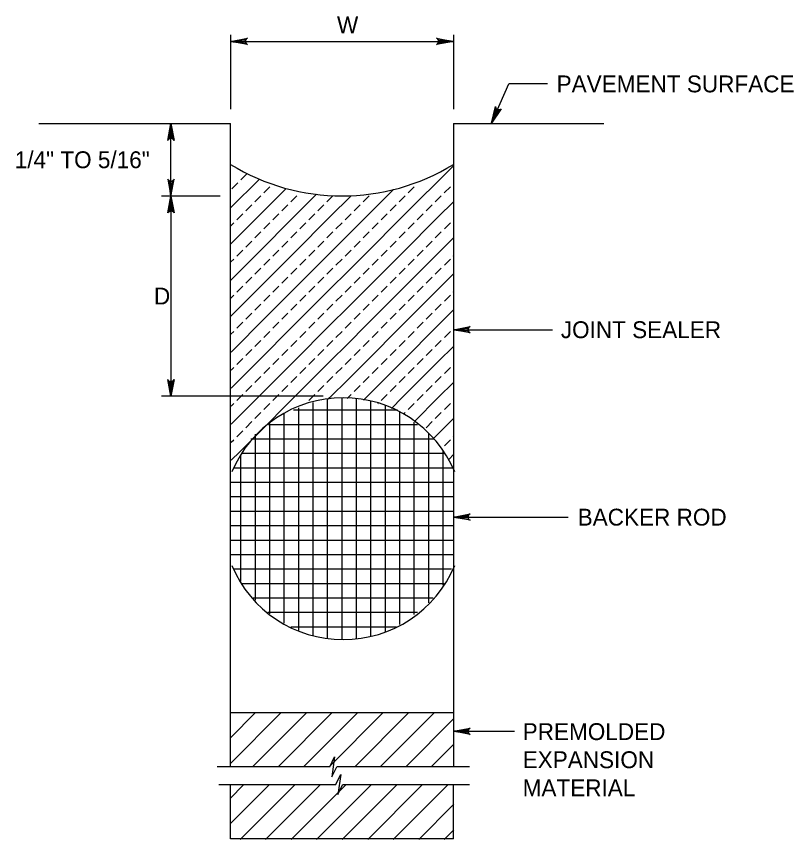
# Model space of a CAD drawing. Extents: x 1.68 to 8.95, y -3.21 to 6.76.
# Drawn here: x 4.101 to 6.867, y 0.817 to 3.746 of the extents above; entities that cross this region are included whole.
import ezdxf

# ---------------------------------------------------------------- set-up
doc = ezdxf.new("R2010")
doc.units = 0
for name, color, linetype in [('DETL-DIMS', 7, 'Continuous'), ('DETL-LINE', 7, 'Continuous'), ('DETL-NOTE', 7, 'Continuous'), ('DETL-PATT', 7, 'Continuous')]:
    doc.layers.add(name, color=color, linetype=linetype)

msp = doc.modelspace()

# ---------------------------------------------------------------- linework, layer by layer
at = {"layer": 'DETL-DIMS'}
for p, q in [((4.863, 3.6802), (4.863, 3.416)), ((5.6563, 3.6802), (5.6563, 3.416)), ((4.863, 3.6573), (5.6563, 3.6573)), ((5.792, 3.3664), (5.8536, 3.5058)), ((5.9915, 3.5058), (5.8536, 3.5058)), ((4.6505, 3.1074), (4.6505, 3.3646)), ((4.6172, 3.1074), (4.8256, 3.1074)), ((4.6505, 3.1074), (4.6505, 2.3943)), ((5.6563, 2.6311), (6.0092, 2.6311)), ((5.1927, 2.3943), (4.6172, 2.3943)), ((5.6563, 1.9641), (6.0653, 1.9641)), ((5.6563, 1.2019), (5.8744, 1.2019))]:
    msp.add_line(p, q, dxfattribs=at)
for points in [[(4.863, 3.6573), (4.923, 3.6685), (4.9184, 3.6653), (4.916, 3.6613), (4.9153, 3.6573), (4.916, 3.6533), (4.9184, 3.6493), (4.923, 3.6461), (4.863, 3.6573), (4.9184, 3.6493), (4.916, 3.6533), (4.863, 3.6573), (4.9153, 3.6573), (4.916, 3.6613), (4.863, 3.6573), (4.9184, 3.6653)], [(4.863, 3.6573), (4.923, 3.6685), (4.9184, 3.6653), (4.916, 3.6613), (4.9153, 3.6573), (4.916, 3.6533), (4.9184, 3.6493), (4.923, 3.6461), (4.863, 3.6573), (4.9184, 3.6493), (4.916, 3.6533), (4.863, 3.6573), (4.9153, 3.6573), (4.916, 3.6613), (4.863, 3.6573), (4.9184, 3.6653)], [(5.6563, 3.6573), (5.5964, 3.6461), (5.601, 3.6493), (5.6034, 3.6533), (5.6041, 3.6573), (5.6034, 3.6613), (5.601, 3.6653), (5.5964, 3.6685), (5.6563, 3.6573), (5.601, 3.6653), (5.6034, 3.6613), (5.6563, 3.6573), (5.6041, 3.6573), (5.6034, 3.6533), (5.6563, 3.6573), (5.601, 3.6493)], [(5.6563, 3.6573), (5.5964, 3.6461), (5.601, 3.6493), (5.6034, 3.6533), (5.6041, 3.6573), (5.6034, 3.6613), (5.601, 3.6653), (5.5964, 3.6685), (5.6563, 3.6573), (5.601, 3.6653), (5.6034, 3.6613), (5.6563, 3.6573), (5.6041, 3.6573), (5.6034, 3.6533), (5.6563, 3.6573), (5.601, 3.6493)], [(5.792, 3.3664), (5.806, 3.4257), (5.807, 3.4202), (5.8097, 3.4164), (5.8131, 3.4141), (5.8171, 3.4131), (5.8217, 3.4137), (5.8265, 3.4166), (5.792, 3.3664), (5.8217, 3.4137), (5.8171, 3.4131), (5.792, 3.3664), (5.8131, 3.4141), (5.8097, 3.4164), (5.792, 3.3664), (5.807, 3.4202)], [(4.6505, 3.3646), (4.6618, 3.3047), (4.6586, 3.3093), (4.6545, 3.3117), (4.6505, 3.3123), (4.6465, 3.3117), (4.6425, 3.3093), (4.6393, 3.3047), (4.6505, 3.3646), (4.6425, 3.3093), (4.6465, 3.3117), (4.6505, 3.3646), (4.6505, 3.3123), (4.6545, 3.3117), (4.6505, 3.3646), (4.6586, 3.3093)], [(4.6507, 3.1064), (4.662, 3.1664), (4.6588, 3.1617), (4.6548, 3.1594), (4.6507, 3.1587), (4.6467, 3.1594), (4.6427, 3.1617), (4.6395, 3.1664), (4.6507, 3.1064), (4.6427, 3.1617), (4.6467, 3.1594), (4.6507, 3.1064), (4.6507, 3.1587), (4.6548, 3.1594), (4.6507, 3.1064), (4.6588, 3.1617)], [(4.6507, 3.1064), (4.662, 3.0465), (4.6588, 3.0511), (4.6548, 3.0535), (4.6507, 3.0542), (4.6467, 3.0535), (4.6427, 3.0511), (4.6395, 3.0465), (4.6507, 3.1064), (4.6427, 3.0511), (4.6467, 3.0535), (4.6507, 3.1064), (4.6507, 3.0542), (4.6548, 3.0535), (4.6507, 3.1064), (4.6588, 3.0511)], [(5.6563, 2.6311), (5.7162, 2.6424), (5.7116, 2.6392), (5.7092, 2.6352), (5.7085, 2.6311), (5.7092, 2.6271), (5.7116, 2.6231), (5.7162, 2.6199), (5.6563, 2.6311), (5.7116, 2.6231), (5.7092, 2.6271), (5.6563, 2.6311), (5.7085, 2.6311), (5.7092, 2.6352), (5.6563, 2.6311), (5.7116, 2.6392)], [(4.6505, 2.3943), (4.6393, 2.4542), (4.6425, 2.4496), (4.6465, 2.4472), (4.6505, 2.4465), (4.6545, 2.4472), (4.6586, 2.4496), (4.6618, 2.4542), (4.6505, 2.3943), (4.6586, 2.4496), (4.6545, 2.4472), (4.6505, 2.3943), (4.6505, 2.4465), (4.6465, 2.4472), (4.6505, 2.3943), (4.6425, 2.4496)], [(5.6563, 1.9641), (5.7162, 1.9753), (5.7116, 1.9721), (5.7092, 1.9681), (5.7085, 1.9641), (5.7092, 1.96), (5.7116, 1.956), (5.7162, 1.9528), (5.6563, 1.9641), (5.7116, 1.956), (5.7092, 1.96), (5.6563, 1.9641), (5.7085, 1.9641), (5.7092, 1.9681), (5.6563, 1.9641), (5.7116, 1.9721)], [(5.6563, 1.9641), (5.7162, 1.9753), (5.7116, 1.9721), (5.7092, 1.9681), (5.7085, 1.9641), (5.7092, 1.96), (5.7116, 1.956), (5.7162, 1.9528), (5.6563, 1.9641), (5.7116, 1.956), (5.7092, 1.96), (5.6563, 1.9641), (5.7085, 1.9641), (5.7092, 1.9681), (5.6563, 1.9641), (5.7116, 1.9721)], [(5.6563, 1.2019), (5.7162, 1.2132), (5.7116, 1.21), (5.7092, 1.2059), (5.7085, 1.2019), (5.7092, 1.1979), (5.7116, 1.1939), (5.7162, 1.1907), (5.6563, 1.2019), (5.7116, 1.1939), (5.7092, 1.1979), (5.6563, 1.2019), (5.7085, 1.2019), (5.7092, 1.2059), (5.6563, 1.2019), (5.7116, 1.21)]]:
    msp.add_lwpolyline(points, dxfattribs=at)
at = {"layer": 'DETL-LINE'}
for p, q in [((4.1808, 3.3646), (4.863, 3.3646)), ((4.863, 1.076), (4.863, 3.3646)), ((5.6563, 3.3646), (5.6563, 1.076)), ((5.6563, 3.3646), (6.1919, 3.3646)), ((5.6562, 3.0218), (5.6565, 3.0221)), ((5.6562, 2.8932), (5.6567, 2.8937)), ((4.864, 2.7439), (4.8741, 2.7539)), ((5.6562, 2.7646), (5.657, 2.7654)), ((5.6562, 2.6361), (5.6572, 2.6371)), ((4.8644, 2.6156), (4.8741, 2.6253)), ((4.8647, 2.4874), (4.8741, 2.4968)), ((5.6562, 2.5075), (5.6575, 2.5088)), ((5.2114, 2.3841), (5.2169, 2.3896)), ((5.2782, 2.3867), (5.2812, 2.3896)), ((5.6562, 2.3789), (5.6577, 2.3804)), ((5.1306, 2.3676), (5.1312, 2.3682)), ((5.3876, 2.3675), (5.3883, 2.3682)), ((4.8955, 2.1968), (4.9598, 2.2611)), ((5.6562, 2.2503), (5.658, 2.2521)), ((4.863, 1.2688), (5.6563, 1.2688)), ((5.216, 1.076), (4.8158, 1.076)), ((5.7135, 1.076), (5.2407, 1.076)), ((5.2369, 1.0117), (4.8217, 1.0117)), ((4.863, 0.8188), (4.863, 1.0117)), ((5.7135, 1.0117), (5.2617, 1.0117)), ((5.6563, 0.8188), (5.6563, 1.0117)), ((5.6563, 0.8188), (4.863, 0.8188))]:
    msp.add_line(p, q, dxfattribs=at)
for points in [[(5.216, 1.076), (5.2332, 1.1112), (5.2235, 1.0398), (5.2407, 1.076)], [(5.2369, 1.0117), (5.255, 1.0487), (5.2453, 0.9773), (5.2617, 1.0117)]]:
    msp.add_lwpolyline(points, dxfattribs=at)
for centre, radius, start, end in [((5.2597, 3.8685), 0.7611, 238.5901, 301.4099), ((5.2642, 1.9586), 0.4304, 22.8516, 157.1484), ((5.2642, 1.9586), 0.4304, 202.8516, 337.1484)]:
    msp.add_arc(centre, radius, start, end, dxfattribs=at)
at = {"layer": 'DETL-PATT'}
for p, q in [((5.4741, 3.0325), (5.6563, 3.2147)), ((4.8632, 3.0645), (4.9654, 3.1667)), ((4.8996, 3.1648), (4.921, 3.1862)), ((4.8674, 3.1327), (4.8889, 3.1541)), ((4.9811, 3.1181), (5.0025, 3.1396)), ((5.4953, 3.1181), (5.5168, 3.1396)), ((5.624, 3.1181), (5.6454, 3.1395)), ((4.9491, 3.0861), (4.9704, 3.1074)), ((4.9598, 3.0325), (5.0611, 3.1338)), ((5.0776, 3.0861), (5.099, 3.1074)), ((5.0883, 3.0325), (5.1687, 3.1129)), ((5.2062, 3.0861), (5.2276, 3.1074)), ((5.2169, 3.0325), (5.2926, 3.1081)), ((5.3348, 3.0861), (5.3561, 3.1074)), ((5.3455, 3.0325), (5.4428, 3.1298)), ((5.4633, 3.0861), (5.4847, 3.1074)), ((5.5919, 3.0861), (5.6133, 3.1074)), ((5.6026, 3.0325), (5.6564, 3.0862)), ((4.9169, 3.0539), (4.9383, 3.0753)), ((5.0455, 3.0539), (5.0669, 3.0753)), ((5.1741, 3.0539), (5.1955, 3.0753)), ((5.3026, 3.0539), (5.3241, 3.0753)), ((5.4312, 3.0539), (5.4526, 3.0753)), ((5.5598, 3.0539), (5.5812, 3.0753)), ((4.8848, 3.0218), (4.8955, 3.0325)), ((4.8955, 3.0325), (4.9062, 3.0432)), ((4.8955, 2.9682), (4.9598, 3.0325)), ((4.9598, 2.9039), (5.0883, 3.0325)), ((5.0133, 3.0218), (5.0241, 3.0325)), ((5.0241, 3.0325), (5.0348, 3.0432)), ((5.0883, 2.9039), (5.2169, 3.0325)), ((5.1419, 3.0218), (5.1526, 3.0325)), ((5.1526, 3.0325), (5.1633, 3.0432)), ((5.2705, 3.0218), (5.2812, 3.0325)), ((5.2812, 3.0325), (5.2919, 3.0432)), ((5.2812, 2.9682), (5.3455, 3.0325)), ((5.3455, 2.9039), (5.4741, 3.0325)), ((5.3991, 3.0218), (5.4098, 3.0325)), ((5.4098, 3.0325), (5.4205, 3.0432)), ((5.4741, 2.9039), (5.6026, 3.0325)), ((5.5276, 3.0218), (5.5383, 3.0325)), ((5.5383, 3.0325), (5.5491, 3.0432)), ((4.8633, 3.0003), (4.8741, 3.0111)), ((4.9812, 2.9896), (5.0026, 3.0111)), ((5.1098, 2.9896), (5.1312, 3.0111)), ((5.2383, 2.9896), (5.2598, 3.0111)), ((5.3669, 2.9896), (5.3883, 3.0111)), ((5.4955, 2.9896), (5.5169, 3.0111)), ((5.6241, 2.9896), (5.6455, 3.0111)), ((4.8635, 2.9362), (4.8955, 2.9682)), ((4.9491, 2.9575), (4.9705, 2.9789)), ((5.0776, 2.9575), (5.0991, 2.9789)), ((5.2062, 2.9575), (5.2276, 2.9789)), ((5.2169, 2.9039), (5.2812, 2.9682)), ((5.3348, 2.9575), (5.3562, 2.9789)), ((5.4633, 2.9575), (5.4848, 2.9789)), ((5.5919, 2.9575), (5.6133, 2.9789)), ((4.9169, 2.9253), (4.9383, 2.9468)), ((5.0455, 2.9253), (5.0669, 2.9468)), ((5.1741, 2.9253), (5.1955, 2.9468)), ((5.3026, 2.9253), (5.3241, 2.9468)), ((5.4312, 2.9253), (5.4526, 2.9468)), ((5.5598, 2.9253), (5.5812, 2.9468)), ((5.6026, 2.9039), (5.6566, 2.9579)), ((4.8848, 2.8932), (4.8955, 2.9039)), ((4.8955, 2.9039), (4.9062, 2.9146)), ((4.8955, 2.8396), (4.9598, 2.9039)), ((4.9598, 2.7753), (5.0883, 2.9039)), ((5.0133, 2.8932), (5.0241, 2.9039)), ((5.0241, 2.9039), (5.0348, 2.9146)), ((5.0883, 2.7753), (5.2169, 2.9039)), ((5.1419, 2.8932), (5.1526, 2.9039)), ((5.1526, 2.9039), (5.1633, 2.9146)), ((5.2705, 2.8932), (5.2812, 2.9039)), ((5.2812, 2.9039), (5.2919, 2.9146)), ((5.2812, 2.8396), (5.3455, 2.9039)), ((5.3455, 2.7753), (5.4741, 2.9039)), ((5.3991, 2.8932), (5.4098, 2.9039)), ((5.4098, 2.9039), (5.4205, 2.9146)), ((5.4741, 2.7753), (5.6026, 2.9039)), ((5.5276, 2.8932), (5.5383, 2.9039)), ((5.5383, 2.9039), (5.5491, 2.9146)), ((4.8637, 2.8721), (4.8741, 2.8825)), ((4.9812, 2.8611), (5.0026, 2.8825)), ((5.1098, 2.8611), (5.1312, 2.8825)), ((5.2383, 2.8611), (5.2598, 2.8825)), ((5.3669, 2.8611), (5.3883, 2.8825)), ((5.4955, 2.8611), (5.5169, 2.8825)), ((5.6241, 2.8611), (5.6455, 2.8825)), ((4.9491, 2.8289), (4.9705, 2.8503)), ((5.0776, 2.8289), (5.0991, 2.8503)), ((5.2062, 2.8289), (5.2276, 2.8503)), ((5.3348, 2.8289), (5.3562, 2.8503)), ((5.4633, 2.8289), (5.4848, 2.8503)), ((5.5919, 2.8289), (5.6133, 2.8503)), ((4.8638, 2.808), (4.8955, 2.8396)), ((4.9169, 2.7968), (4.9383, 2.8182)), ((5.0455, 2.7968), (5.0669, 2.8182)), ((5.1741, 2.7968), (5.1955, 2.8182)), ((5.2169, 2.7753), (5.2812, 2.8396)), ((5.3026, 2.7968), (5.3241, 2.8182)), ((5.4312, 2.7968), (5.4526, 2.8182)), ((5.5598, 2.7968), (5.5812, 2.8182)), ((5.6026, 2.7753), (5.6569, 2.8296)), ((4.8955, 2.7753), (4.9062, 2.7861)), ((5.0241, 2.7753), (5.0348, 2.7861)), ((5.1526, 2.7753), (5.1633, 2.7861)), ((5.2812, 2.7753), (5.2919, 2.7861)), ((5.4098, 2.7753), (5.4205, 2.7861)), ((5.5383, 2.7753), (5.5491, 2.7861)), ((4.8848, 2.7646), (4.8955, 2.7753)), ((4.8955, 2.7111), (4.9598, 2.7753)), ((4.9598, 2.6468), (5.0883, 2.7753)), ((4.9812, 2.7325), (5.0026, 2.7539)), ((5.0133, 2.7646), (5.0241, 2.7753)), ((5.0883, 2.6468), (5.2169, 2.7753)), ((5.1098, 2.7325), (5.1312, 2.7539)), ((5.1419, 2.7646), (5.1526, 2.7753)), ((5.2383, 2.7325), (5.2598, 2.7539)), ((5.2705, 2.7646), (5.2812, 2.7753)), ((5.2812, 2.7111), (5.3455, 2.7753)), ((5.3455, 2.6468), (5.4741, 2.7753)), ((5.3669, 2.7325), (5.3883, 2.7539)), ((5.3991, 2.7646), (5.4098, 2.7753)), ((5.4741, 2.6468), (5.6026, 2.7753)), ((5.4955, 2.7325), (5.5169, 2.7539)), ((5.5276, 2.7646), (5.5383, 2.7753)), ((5.6241, 2.7325), (5.6455, 2.7539)), ((4.8642, 2.6798), (4.8955, 2.7111)), ((4.9491, 2.7003), (4.9705, 2.7218)), ((5.0776, 2.7003), (5.0991, 2.7218)), ((5.2062, 2.7003), (5.2276, 2.7218)), ((5.2169, 2.6468), (5.2812, 2.7111)), ((5.3348, 2.7003), (5.3562, 2.7218)), ((5.4633, 2.7003), (5.4848, 2.7218)), ((5.5919, 2.7003), (5.6133, 2.7218)), ((5.6026, 2.6468), (5.6571, 2.7013)), ((4.9169, 2.6682), (4.9383, 2.6896)), ((5.0455, 2.6682), (5.0669, 2.6896)), ((5.1741, 2.6682), (5.1955, 2.6896)), ((5.3026, 2.6682), (5.3241, 2.6896)), ((5.4312, 2.6682), (5.4526, 2.6896)), ((5.5598, 2.6682), (5.5812, 2.6896)), ((4.8848, 2.6361), (4.8955, 2.6468)), ((4.8955, 2.6468), (4.9062, 2.6575)), ((4.8955, 2.5825), (4.9598, 2.6468)), ((4.9598, 2.5182), (5.0883, 2.6468)), ((5.0133, 2.6361), (5.0241, 2.6468)), ((5.0241, 2.6468), (5.0348, 2.6575)), ((5.0883, 2.5182), (5.2169, 2.6468)), ((5.1419, 2.6361), (5.1526, 2.6468)), ((5.1526, 2.6468), (5.1633, 2.6575)), ((5.2705, 2.6361), (5.2812, 2.6468)), ((5.2812, 2.6468), (5.2919, 2.6575)), ((5.2812, 2.5825), (5.3455, 2.6468)), ((5.3455, 2.5182), (5.4741, 2.6468)), ((5.3991, 2.6361), (5.4098, 2.6468)), ((5.4098, 2.6468), (5.4205, 2.6575)), ((5.4741, 2.5182), (5.6026, 2.6468)), ((5.5276, 2.6361), (5.5383, 2.6468)), ((5.5383, 2.6468), (5.5491, 2.6575)), ((4.9812, 2.6039), (5.0026, 2.6253)), ((5.1098, 2.6039), (5.1312, 2.6253)), ((5.2383, 2.6039), (5.2598, 2.6253)), ((5.3669, 2.6039), (5.3883, 2.6253)), ((5.4955, 2.6039), (5.5169, 2.6253)), ((5.6241, 2.6039), (5.6455, 2.6253)), ((4.8645, 2.5515), (4.8955, 2.5825)), ((4.9491, 2.5718), (4.9705, 2.5932)), ((5.0776, 2.5718), (5.0991, 2.5932)), ((5.2062, 2.5718), (5.2276, 2.5932)), ((5.2169, 2.5182), (5.2812, 2.5825)), ((5.3348, 2.5718), (5.3562, 2.5932)), ((5.4633, 2.5718), (5.4848, 2.5932)), ((5.5919, 2.5718), (5.6133, 2.5932)), ((4.9169, 2.5396), (4.9383, 2.5611)), ((5.0455, 2.5396), (5.0669, 2.5611)), ((5.1741, 2.5396), (5.1955, 2.5611)), ((5.3026, 2.5396), (5.3241, 2.5611)), ((5.4312, 2.5396), (5.4526, 2.5611)), ((5.5598, 2.5396), (5.5812, 2.5611)), ((5.6026, 2.5182), (5.6574, 2.5729)), ((4.8955, 2.5182), (4.9062, 2.5289)), ((5.0241, 2.5182), (5.0348, 2.5289)), ((5.1526, 2.5182), (5.1633, 2.5289)), ((5.2812, 2.5182), (5.2919, 2.5289)), ((5.4098, 2.5182), (5.4205, 2.5289)), ((5.5383, 2.5182), (5.5491, 2.5289)), ((4.8848, 2.5075), (4.8955, 2.5182)), ((4.8955, 2.4539), (4.9598, 2.5182)), ((4.9598, 2.3896), (5.0883, 2.5182)), ((4.9812, 2.4753), (5.0026, 2.4968)), ((5.0133, 2.5075), (5.0241, 2.5182)), ((5.0883, 2.3896), (5.2169, 2.5182)), ((5.1098, 2.4753), (5.1312, 2.4968)), ((5.1419, 2.5075), (5.1526, 2.5182)), ((5.2383, 2.4753), (5.2598, 2.4968)), ((5.2705, 2.5075), (5.2812, 2.5182)), ((5.2812, 2.4539), (5.3455, 2.5182)), ((5.3455, 2.3896), (5.4741, 2.5182)), ((5.3669, 2.4753), (5.3883, 2.4968)), ((5.3991, 2.5075), (5.4098, 2.5182)), ((5.4741, 2.3896), (5.6026, 2.5182)), ((5.4955, 2.4753), (5.5169, 2.4968)), ((5.5276, 2.5075), (5.5383, 2.5182)), ((5.6241, 2.4753), (5.6455, 2.4968)), ((4.9491, 2.4432), (4.9705, 2.4646)), ((5.0776, 2.4432), (5.0991, 2.4646)), ((5.2062, 2.4432), (5.2276, 2.4646)), ((5.3348, 2.4432), (5.3562, 2.4646)), ((5.4633, 2.4432), (5.4848, 2.4646)), ((5.5919, 2.4432), (5.6133, 2.4646)), ((4.8649, 2.4233), (4.8955, 2.4539)), ((4.9169, 2.4111), (4.9383, 2.4325)), ((5.0455, 2.4111), (5.0669, 2.4325)), ((5.1741, 2.4111), (5.1955, 2.4325)), ((5.2169, 2.3896), (5.2812, 2.4539)), ((5.3026, 2.4111), (5.3241, 2.4325)), ((5.4312, 2.4111), (5.4526, 2.4325)), ((5.5598, 2.4111), (5.5812, 2.4325)), ((5.6026, 2.3896), (5.6576, 2.4446)), ((4.8848, 2.3789), (4.8955, 2.3896)), ((4.8955, 2.3896), (4.9062, 2.4003)), ((4.8955, 2.3253), (4.9598, 2.3896)), ((4.9598, 2.2611), (5.0883, 2.3896)), ((5.0133, 2.3789), (5.0241, 2.3896)), ((5.0241, 2.3896), (5.0348, 2.4003)), ((5.1419, 2.3789), (5.1526, 2.3896)), ((5.1526, 2.3896), (5.1633, 2.4003)), ((5.2084, 1.5306), (5.2084, 2.3842)), ((5.2598, 1.5277), (5.2598, 2.3884)), ((5.2812, 2.3896), (5.2919, 2.4003)), ((5.3113, 1.5322), (5.3113, 2.3842)), ((5.3366, 2.3807), (5.3455, 2.3896)), ((5.3627, 1.5393), (5.3627, 2.3796)), ((5.3991, 2.3789), (5.4098, 2.3896)), ((5.4098, 2.3896), (5.4205, 2.4003)), ((5.4356, 2.3512), (5.4741, 2.3896)), ((5.5177, 2.3047), (5.6026, 2.3896)), ((5.5276, 2.3789), (5.5383, 2.3896)), ((5.5383, 2.3896), (5.5491, 2.4003)), ((4.865, 2.3592), (4.8741, 2.3682)), ((4.9812, 2.3468), (5.0026, 2.3682)), ((5.0867, 2.3456), (5.457, 2.3456)), ((5.1056, 1.5595), (5.1056, 2.3527)), ((5.157, 1.5423), (5.157, 2.3723)), ((5.4141, 1.5569), (5.4141, 2.364)), ((5.4955, 2.3468), (5.5169, 2.3682)), ((5.6241, 2.3468), (5.6455, 2.3682)), ((4.8652, 2.2951), (4.8955, 2.3253)), ((4.9491, 2.3146), (4.9705, 2.3361)), ((5.0541, 1.5867), (5.0541, 2.3331)), ((5.4656, 1.5821), (5.4656, 2.3395)), ((5.4792, 2.3305), (5.4848, 2.3361)), ((5.5919, 2.3146), (5.6133, 2.3361)), ((5.6026, 2.2611), (5.6579, 2.3163)), ((4.9169, 2.2825), (4.9383, 2.3039)), ((4.9983, 2.2941), (5.5287, 2.2941)), ((5.0027, 1.6204), (5.0027, 2.2974)), ((5.517, 1.6176), (5.517, 2.3025)), ((5.5598, 2.2825), (5.5812, 2.3039)), ((4.8848, 2.2503), (4.8955, 2.2611)), ((4.8955, 2.2611), (4.9062, 2.2718)), ((4.9513, 1.6685), (4.9513, 2.2593)), ((5.5684, 1.6591), (5.5684, 2.2619)), ((5.5858, 2.2442), (5.6026, 2.2611)), ((4.8654, 2.2309), (4.8741, 2.2396)), ((4.9355, 2.2427), (5.5876, 2.2427)), ((5.6241, 2.2182), (5.6455, 2.2396)), ((5.6198, 1.7221), (5.6198, 2.1982)), ((4.8655, 2.1668), (4.8955, 2.1968)), ((4.8998, 1.7363), (4.8998, 2.1815)), ((4.9056, 2.1913), (5.6247, 2.1913)), ((5.6397, 2.1695), (5.6581, 2.188)), ((4.8756, 2.1398), (5.6545, 2.1398)), ((4.8656, 2.0884), (5.6558, 2.0884)), ((4.8656, 2.037), (5.6555, 2.037)), ((4.8656, 1.9856), (5.6551, 1.9856)), ((4.8656, 1.9341), (5.6548, 1.9341)), ((4.8656, 1.8827), (5.6545, 1.8827)), ((4.8656, 1.8313), (5.6542, 1.8313)), ((4.8762, 1.7798), (5.6495, 1.7798)), ((4.9041, 1.7284), (5.6231, 1.7284)), ((4.9428, 1.677), (5.5844, 1.677)), ((4.9952, 1.6256), (5.5279, 1.6256)), ((5.0779, 1.5741), (5.4536, 1.5741)), ((4.8623, 1.1788), (4.9509, 1.2673)), ((4.8623, 1.0879), (5.0418, 1.2673)), ((4.9423, 1.0769), (5.1327, 1.2673)), ((5.0332, 1.0769), (5.2236, 1.2673)), ((5.1241, 1.0769), (5.3145, 1.2673)), ((5.215, 1.0769), (5.4054, 1.2673)), ((5.306, 1.0769), (5.4963, 1.2673)), ((5.3969, 1.0769), (5.5873, 1.2673)), ((5.4878, 1.0769), (5.6569, 1.246)), ((5.5787, 1.0769), (5.6569, 1.1551)), ((4.8623, 0.9643), (4.9081, 1.0101)), ((4.8623, 0.8734), (4.999, 1.0101)), ((4.8967, 0.8168), (5.09, 1.0101)), ((4.9876, 0.8168), (5.1809, 1.0101)), ((5.0785, 0.8168), (5.2718, 1.0101)), ((5.1694, 0.8168), (5.3627, 1.0101)), ((5.2603, 0.8168), (5.4536, 1.0101)), ((5.3512, 0.8168), (5.5445, 1.0101)), ((5.4421, 0.8168), (5.6354, 1.0101)), ((5.5331, 0.8168), (5.6583, 0.9421)), ((5.624, 0.8168), (5.6583, 0.8511))]:
    msp.add_line(p, q, dxfattribs=at)

# ---------------------------------------------------------------- texts
at = {"layer": 'DETL-NOTE'}
for s, p in [('W', (5.2418, 3.6859)), ('PAVEMENT SURFACE', (6.0238, 3.4758)), ('1/4" TO 5/16"', (4.0945, 3.206)), ('D', (4.5901, 2.7209)), ('JOINT SEALER', (6.0387, 2.6011)), ('BACKER ROD', (6.0987, 1.9341)), ('PREMOLDED', (5.9029, 1.1708)), ('EXPANSION', (5.9029, 1.0708)), ('MATERIAL', (5.9029, 0.9708))]:
    msp.add_text(s, height=0.06, dxfattribs=at).set_placement(p)

doc.saveas('drawing.dxf')
